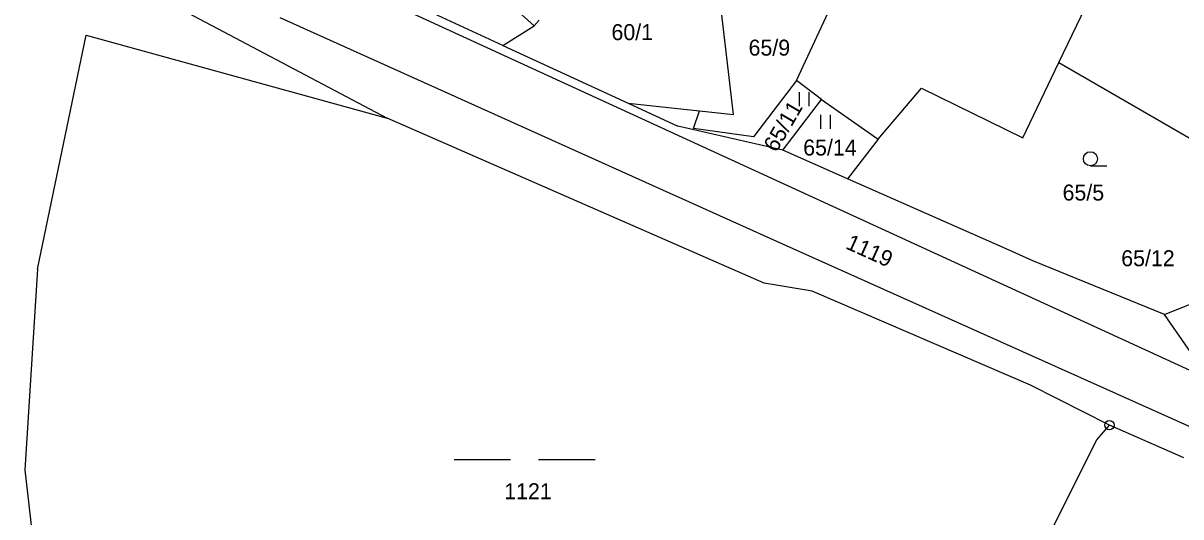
# Model space of a CAD drawing. Extents: x -796130 to -793145, y -1109506 to -1106267.
# Drawn here: x -794442.6 to -794319.4, y -1107964 to -1107911.5 of the extents above; entities that cross this region are included whole.
import ezdxf

# ---------------------------------------------------------------- set-up
doc = ezdxf.new("R2010")
doc.units = 0
for name, color, linetype in [('Vrstva 1', 7, 'Continuous'), ('Vrstva 14', 7, 'Continuous'), ('Vrstva 16', 7, 'Continuous'), ('Vrstva 2', 7, 'Continuous'), ('Vrstva 23', 7, 'Continuous'), ('Vrstva 28', 7, 'Continuous')]:
    doc.layers.add(name, color=color, linetype=linetype)

msp = doc.modelspace()

# ---------------------------------------------------------------- linework, layer by layer
at = {"layer": 'Vrstva 1'}
for p, q in [((-794447.88, -1107898.28), (-794403.89, -1107921.59)), ((-794388.26, -1107911.75), (-794399.48, -1107901.64)), ((-794391.58, -1107913.85), (-794405.89, -1107907.21)), ((-794360.32, -1107917.58), (-794355.91, -1107908.06)), ((-794332.4, -1107915.66), (-794328.77, -1107908.05)), ((-794391.58, -1107913.85), (-794388.26, -1107911.75)), ((-794388.26, -1107911.75), (-794387.73, -1107911.15)), ((-794441.1, -1107937.63), (-794435.94, -1107912.75)), ((-794435.94, -1107912.75), (-794403.89, -1107921.59)), ((-794391.58, -1107913.85), (-794378.26, -1107919.99)), ((-794336.24, -1107923.65), (-794332.4, -1107915.66)), ((-794332.4, -1107915.66), (-794318.28, -1107923.8)), ((-794360.32, -1107917.58), (-794364.9, -1107923.56)), ((-794357.68, -1107919.58), (-794360.32, -1107917.58)), ((-794351.63, -1107923.82), (-794347.04, -1107918.4)), ((-794347.04, -1107918.4), (-794336.24, -1107923.65)), ((-794378.26, -1107919.99), (-794370.64, -1107920.8)), ((-794378.26, -1107919.99), (-794372.96, -1107922.44)), ((-794361.77, -1107924.98), (-794357.68, -1107919.58)), ((-794357.68, -1107919.58), (-794351.63, -1107923.82)), ((-794363.78, -1107939.12), (-794403.89, -1107921.59)), ((-794371.29, -1107922.69), (-794370.64, -1107920.8)), ((-794361.77, -1107924.98), (-794372.96, -1107922.44)), ((-794364.9, -1107923.56), (-794371.29, -1107922.69)), ((-794351.63, -1107923.82), (-794354.89, -1107928.02)), ((-794354.89, -1107928.02), (-794361.77, -1107924.98)), ((-794338.02, -1107935.48), (-794354.89, -1107928.02)), ((-794335.16, -1107936.74), (-794338.02, -1107935.48)), ((-794441.1, -1107937.63), (-794442.46, -1107959.01)), ((-794321.16, -1107942.45), (-794335.16, -1107936.74)), ((-794358.65, -1107940), (-794363.78, -1107939.12)), ((-794335.41, -1107949.99), (-794358.65, -1107940)), ((-794321.16, -1107942.45), (-794313.79, -1107939.52)), ((-794318.35, -1107946.5), (-794321.16, -1107942.45)), ((-794327.03, -1107954.23), (-794335.41, -1107949.99)), ((-794328.35, -1107955.8), (-794327.03, -1107954.23)), ((-794319.11, -1107957.73), (-794327.03, -1107954.23)), ((-794335.13, -1107969.27), (-794328.35, -1107955.8)), ((-794442.46, -1107959.01), (-794440.99, -1107971.78))]:
    msp.add_line(p, q, dxfattribs=at)
msp.add_lwpolyline([(-794370.64, -1107920.8), (-794367.05, -1107921.18), (-794368.48, -1107908.74)], dxfattribs=at)
at = {"layer": 'Vrstva 2'}
for p, q in [((-794299.63, -1107957.06), (-794407.86, -1107907.36)), ((-794415.3, -1107910.85), (-794361.74, -1107934.98)), ((-794361.74, -1107934.98), (-794302.78, -1107961.45))]:
    msp.add_line(p, q, dxfattribs=at)
at = {"layer": 'Vrstva 23'}
for p, q in [((-794360.01, -1107920.3), (-794360.01, -1107918.8)), ((-794359.01, -1107918.8), (-794359.01, -1107920.3)), ((-794357.73, -1107922.72), (-794357.73, -1107921.22)), ((-794356.73, -1107921.22), (-794356.73, -1107922.72)), ((-794329.05, -1107926.65), (-794327.3, -1107926.65)), ((-794396.77, -1107957.91), (-794390.77, -1107957.91)), ((-794387.77, -1107957.91), (-794381.77, -1107957.91))]:
    msp.add_line(p, q, dxfattribs=at)
msp.add_circle((-794329.05, -1107925.9), 0.75, dxfattribs=at)
at = {"layer": 'Vrstva 28'}
for radius in [0.5, 0.01]:
    msp.add_circle((-794327.03, -1107954.23), radius, dxfattribs=at)

# ---------------------------------------------------------------- texts
at = {"layer": 'Vrstva 14'}
for s, p in [('60/1', (-794380.02, -1107913.27)), ('65/9', (-794365.43, -1107914.92)), ('65/14', (-794359.615, -1107925.55)), ('65/5', (-794332.01, -1107930.34)), ('1121', (-794391.436, -1107962.12))]:
    msp.add_text(s, height=1.7, dxfattribs=at).set_placement(p)
for s, rotation, p in [('65/11', 59.76432, (-794362.467, -1107925.307)), ('1119', 335.7, (-794355.196, -1107935.406))]:
    msp.add_text(s, height=1.7, rotation=rotation, dxfattribs=at).set_placement(p)
at = {"layer": 'Vrstva 16'}
msp.add_text('65/12', height=1.7, dxfattribs=at).set_placement((-794325.769, -1107937.33))

doc.saveas('drawing.dxf')
